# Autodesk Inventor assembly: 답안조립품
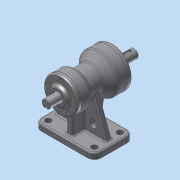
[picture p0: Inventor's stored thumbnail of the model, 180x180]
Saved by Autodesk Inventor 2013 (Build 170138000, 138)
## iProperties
Created: 2015-08
Part Number: 답안조립품
Document SubType Name: Assembly
Designer: Administrator
Author: Administrator
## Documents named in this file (10)
- C:\Users\Administrator\Desktop\450806v1006\답안조립품.iam
- C:\Users\Administrator\Desktop\450806v1006\본체.ipt
- C:\Users\Administrator\Desktop\450806v1006\축.ipt
- C:\Users\Administrator\Desktop\450806v1006\앞커버.ipt
- C:\Users\Administrator\Desktop\450806v1006\뒤커버.ipt
- C:\Users\Administrator\Desktop\450806v1006\베어링 6203.ipt
- C:\Users\Administrator\Desktop\450806v1006\베어링 6205.ipt
- C:\Users\Administrator\Desktop\450806v1006\오일실 .ipt
- 오일실 .ipt
- C:\Users\Administrator\Desktop\450806v1006\M4x0.5.ipt
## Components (10 placed, 1 different names)
1. M4x0.5:1
2. M4x0.5:2
3. M4x0.5:3
4. M4x0.5:4
5. M4x0.5:5
6. M4x0.5:6
7. M4x0.5:7
8. M4x0.5:8
9. M4x0.5:9
10. M4x0.5:10
